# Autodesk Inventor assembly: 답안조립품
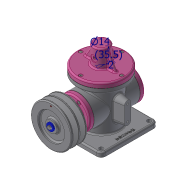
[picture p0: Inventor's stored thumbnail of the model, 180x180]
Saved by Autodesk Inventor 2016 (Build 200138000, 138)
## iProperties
Created: 2020-02
Part Number: 답안조립품
Material: 일반
Document SubType Name: Assembly
Designer: Administrator
Mass: 2562.92 g
Surface Area: 2485.6 cm^2
Volume: 789.842 cm^3
Density: 3.24485 g/cm^3
Author: Administrator
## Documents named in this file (21)
- C:\Users\Administrator\Desktop\600206V1012\답안조립품.iam
- C:\Users\Administrator\Desktop\600206V1012\본체.ipt
- C:\Users\Administrator\Desktop\600206V1012\볼트 M4 x 10.ipt
- C:\Users\Administrator\Desktop\600206V1012\슬라이더.ipt
- C:\Users\Administrator\Desktop\600206V1012\앞커버.ipt
- C:\Users\Administrator\Desktop\600206V1012\오일 실 17 30 8.ipt
- C:\Users\Administrator\Desktop\600206V1012\와셔 4x16.ipt
- C:\Users\Administrator\Desktop\600206V1012\육각 소켓 머리 볼트 M4 x 10.ipt
- C:\Users\Administrator\Desktop\600206V1012\클레비스 핀 6 x 22.ipt
- 클레비스 핀 6 x 22.ipt
- C:\Users\Administrator\Desktop\600206V1012\키 4 x 4 x 25.ipt
- C:\Users\Administrator\Desktop\600206V1012\편심축.ipt
- C:\Users\Administrator\Desktop\600206V1012\E-링.ipt
- C:\Users\Administrator\Desktop\600206V1012\V-벨트풀리.ipt
- C:\Users\Administrator\Desktop\600206V1012\가변스프링.ipt
- C:\Users\Administrator\Desktop\600206V1012\개스킷 A.ipt
- C:\Users\Administrator\Desktop\600206V1012\개스킷 B.ipt
- C:\Users\Administrator\Desktop\600206V1012\덮개.ipt
- C:\Users\Administrator\Desktop\600206V1012\뒤커버.ipt
- C:\Users\Administrator\Desktop\600206V1012\링크.ipt
- C:\Users\Administrator\Desktop\600206V1012\베어링 17 x 40 x 12.ipt
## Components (6 placed, 5 different names)
1. E-링:1
2. V-벨트풀리:1 — 각도:2, 플러쉬:1
3. 가변스프링:1
4. 개스킷 A:1
5. 개스킷 B:1
6. 개스킷 A:2
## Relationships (2: Angle 1, Flush 1)
- 각도:2 [Angle]: V-벨트풀리:1
- 플러쉬:1 [Flush]: V-벨트풀리:1
